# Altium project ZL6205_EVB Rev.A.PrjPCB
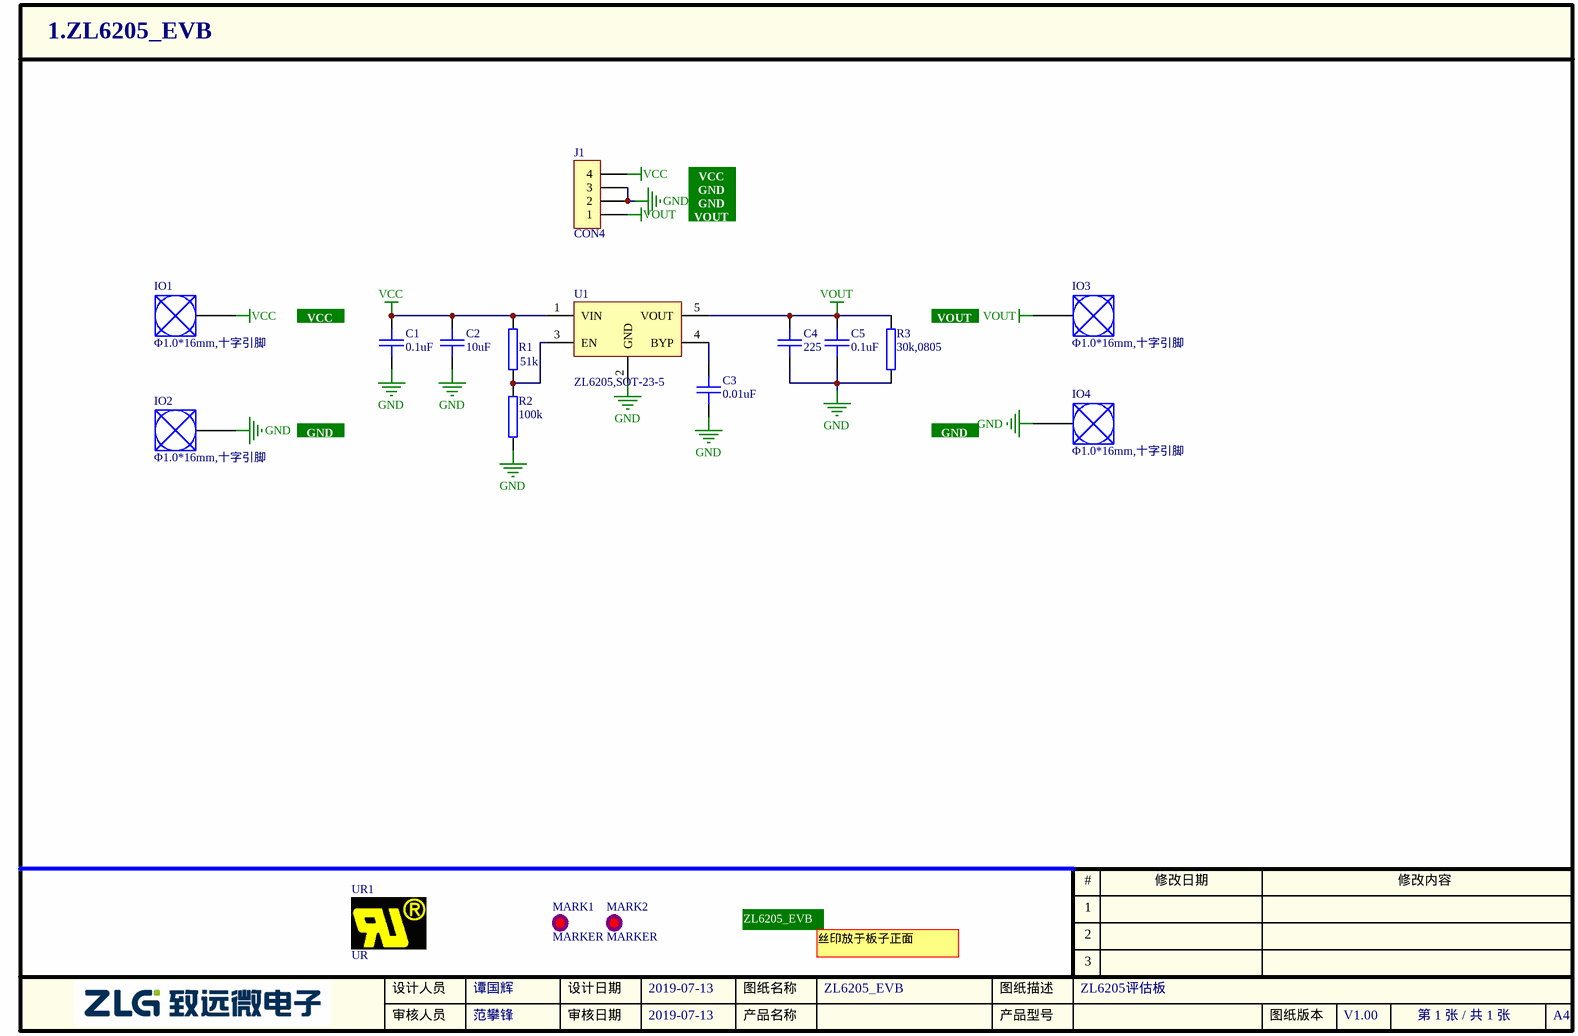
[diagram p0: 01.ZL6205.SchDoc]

1 sheet, 17 parts. Net scope: global (net labels, ports and power ports of the same name join across sheets).
Board file: ZL6205_EVB Rev.A.PcbDoc

## Sheet 01.ZL6205.SchDoc
size A4; CheckedBy: 范攀锋; Author: 谭国辉; CompanyName: 广州立功科技股份有限公司; DocumentNumber: 1; SheetNumber: 1; SheetTotal: 1; PageSetup: Record=PageOptions|CenterHorizontal=True|CenterVertical=True|PrintScale=1.00|XCorrection=1.00|YCorrection=1.00|PrintKind=0|BorderSize=5000000|LeftOffset=0|BottomOffset=0|Orientation=2|PaperLength=1000|PaperWidth=1000|Scale=100|PaperSource=7|PrintQuality=600|MediaType=1|DitherType=10|PaperKind=A4|PrintScaleMode=1; DesignDate: 2019-07-13; CheckDate: 2019-07-13; SheetName: ZL6205_EVB; SheetVersion: V1.00; SheetDescription: ZL6205评估板

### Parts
C1  0.1uF  [0603C]  (no BOM)
C2  10uF  [0805C]
C3  0.01uF  [0603C]
C4  225  [0805C]
C5  0.1uF  [0603C]  (no BOM)
IO1  Φ1.0*16mm,十字引脚  [HOLE-1.15X2.6]
IO2  Φ1.0*16mm,十字引脚  [HOLE-1.15X2.6]
IO3  Φ1.0*16mm,十字引脚  [HOLE-1.15X2.6]
IO4  Φ1.0*16mm,十字引脚  [HOLE-1.15X2.6]
J1  CON4  [SIP-4-2.54]
MARK1  MARKER  [MARKER-C-0.8M]  (no BOM)
MARK2  MARKER  [MARKER-C-0.8M]  (no BOM)
R1  51k  [0603R]
R2  100k  [0603R]
R3  30k,0805  [0805R]
U1  ZL6205,SOT-23-5
UR1  UR  [ZY_UR-3X2]  (no BOM)

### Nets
GND: C1.2 C2.2 C3.2 C4.2 C5.2 IO2.1 IO4.1 J1.2 J1.3 R2.1 R3.1 U1.2(GND)
VCC: C1.1 C2.1 IO1.1 J1.4 R1.2 U1.1(VIN)
VOUT: C4.1 C5.1 IO3.1 J1.1 R3.2 U1.5(VOUT)
NetC3_1: C3.1 U1.4(BYP)
NetR1_1: R1.1 R2.2 U1.3(EN)

Not connected (* = marked no-connect by the designer): MARK1 0; MARK2 0

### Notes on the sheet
- VCC
  GND
  GND
  VOUT
- (near C1) VCC
- (near R3) VOUT
- GND
- ZL6205_EVB
- 丝印放于板子正面

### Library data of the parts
C1 C5 = 02.01.00015: C1608X7R1H104KT000N,0603,TDK,0.1uF,X7R,±10%,50V,; 旧物料代码: 1.02.01.0072; 名称: 电容; 封装: 0603; 贴片和直插: SMT; PCB备注: 151110lmd; 器件优选方案: 不推荐使用
C2 = 02.01.00174: GRM21BR61A106KE19L,0805,MURATA,10uF,X5R,±10%,10V,; 旧物料代码: 1.02.02.0055; 名称: 电容; 封装: 0805; 贴片和直插: SMT; 器件优选方案: 不推荐使用
C3 = 02.01.00364: GCM188R71H103KA15D,103,±10%,50V,X7R,0603,MURATA,; 旧物料代码: 1.02.01.0090; 名称: 电容; 封装: 0603; 贴片和直插: SMT; PCB备注: 180305ZW; 器件优选方案: 不推荐使用
C4 = 02.01.00194: C2012X7R1C225KT000N,0805,TDK,2.2uF,X7R,±10%,16V,; 旧物料代码: 1.02.02.0087; 名称: 电容; 封装: 0805; 贴片和直插: SMT; PCB备注: 160218lmd; 器件优选方案: 不推荐使用
IO1-IO4 = 24.05.00031: Φ1.0*16mm,十字引脚,黄铜,; 旧物料代码: 1.15.06.0055; 名称: 金属端子; 封装: THT; PCB备注: 161130 HCJ; 器件优选方案: 定制物料
J1 = CON4: Connector
R1 = 01.01.00073: RTT035102DTP,0603,RALEC,51KΩ,±0.5%,1/10W,; 旧物料代码: 1.01.01.0091; 名称: 电阻; 封装: 0603; 贴片和直插: SMT; 器件优选方案: 通用物料
R2 = 01.01.00031: RTT03104JTP,0603,RALEC,100KΩ,±5%,1/10W,; 旧物料代码: 1.01.01.0062; 名称: 电阻; 封装: 0603; 贴片和直插: SMT; 器件优选方案: 通用物料
R3 = 01.01.00305: RTT05303JTP,0805,RALEC,30KΩ,±5%,1/8W,; 旧物料代码: 1.01.02.0083; 名称: 电阻; 封装: 0805; 贴片和直插: SMT; 器件优选方案: 通用物料
U1 = ZL6205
